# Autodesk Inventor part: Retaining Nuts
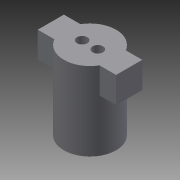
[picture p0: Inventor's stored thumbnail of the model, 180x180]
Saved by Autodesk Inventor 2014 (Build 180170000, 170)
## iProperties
Created: 2013-11
Part Number: Retaining Nuts
Material: Generic
Document SubType Name: Modeling
Designer: 603839
Density: 1 g/cm^3
Appearance: Default
Mass: 2.49841 g
Surface Area: 14.8326 cm^2
Volume: 2.49841 cm^3
Author: 603839
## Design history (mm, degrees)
sketch "Sketch1"
  geometry: C1 r 6.35 at (0, 0); 1 further point
  constraints: 1 centre point, 1 coincident
  dimensions: "d0" = 12.7 diameter of C1
extrude "Extrusion1" new body sketch "Sketch1" distance "d1" = 12.7; taper "d2" = 0 deg
sketch "Sketch2"
  geometry: L1 (-9.525, -3.175)-(9.525, -3.175); L2 (9.525, -3.175)-(9.525, 3.175); L3 (9.525, 3.175)-(-9.525, 3.175); L4 (-9.525, 3.175)-(-9.525, -3.175); L5 (-9.525, -3.175)-(9.525, 3.175); L6 (9.525, -3.175)-(-9.525, 3.175); C1 r 6.35 at (0, 0) reference
  constraints: 12 end point, 2 midpoint, 2 parallel, 1 horizontal, 1 perpendicular
  dimensions: "d3" = 19.05 distance of L1.start L1.end; "d4" = 6.35 distance of L2.end L1.end
extrude "Extrusion2" join sketch "Sketch2" distance "d5" = 6.35; taper "d6" = 0 deg
sketch "Sketch3"
  geometry: L1 (5.499, -3.175)-(-5.499, -3.175) reference; A1 r 6.35 centre (0, 0) between (-5.499, -3.175) and (5.499, -3.175) reference
extrude "Extrusion3" join sketch "Sketch3" distance "d7" = 6.35; taper "d8" = 0 deg
sketch "Sketch4"
  geometry: L1 (-5.499, 3.175)-(5.499, 3.175) reference; A1 r 6.35 centre (0, 0) between (5.499, 3.175) and (-5.499, 3.175) reference
extrude "Extrusion4" join sketch "Sketch4" distance "d9" = 6.35; taper "d10" = 0 deg
sketch "Sketch5"
  geometry: L1 (-9.525, 3.175)-(9.525, 3.175); L2 (9.525, 3.175)-(9.525, -3.175); L3 (9.525, -3.175)-(-9.525, -3.175); L4 (-9.525, -3.175)-(-9.525, 3.175); L5 (-9.525, -3.175)-(9.525, 3.175); L6 (9.525, -3.175)-(-9.525, 3.175); L7 (0, 0)-(1.905, 0); L8 (0, 0)-(-1.905, 0); A1 r 6.35 centre (0, 0) between (5.499, 3.175) and (-5.499, 3.175) reference
  constraints: 16 end point, 3 equal length, 2 perpendicular, 1 horizontal
  dimensions: "d11" = 1.905 distance of L7.start L7.end; "d12" = 1.905 distance of L7.start L8.end
hole "Hole1" sketch "Sketch5" at (-1.905, 0) diameter "d13" = 2.54; stored, may be unused: countersink angle "d17" = 82 deg, drill point angle "d19" = 0 deg; dims "d14" = 19.05, "d15" = 9.525, "d16" = 6.35, "d18" = 25.4
sketch "Sketch6"
  geometry: L1 (-9.525, 3.175)-(-9.525, -3.175) reference; L2 (0, 0)-(1.905, 0); A1 r 6.35 centre (0, 0) between (5.499, 3.175) and (-5.499, 3.175) reference
  constraints: 2 end point, 1 perpendicular
  dimensions: "d20" = 1.905 distance of L2.start L2.end
hole "Hole2" sketch "Sketch6" at (1.905, 0) diameter "d21" = 2.54; stored, may be unused: countersink angle "d25" = 82 deg, drill point angle "d27" = 0 deg; dims "d22" = 19.05, "d23" = 9.525, "d24" = 6.35, "d26" = 25.4
body "Solid1"
